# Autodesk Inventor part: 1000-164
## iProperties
Created: 2007-03
Part Number: 1000-164
Document SubType Name: Modeling
Designer: Andy Moles
Material: Steel
Density: 7.85 g/cm^3
Mass: 11.4961 g
Surface Area: 15.9382 cm^2
Volume: 1.46447 cm^3
Author: Andy Moles
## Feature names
1. Base1
